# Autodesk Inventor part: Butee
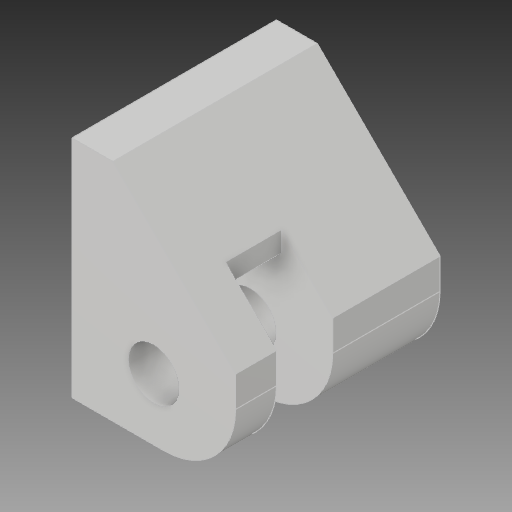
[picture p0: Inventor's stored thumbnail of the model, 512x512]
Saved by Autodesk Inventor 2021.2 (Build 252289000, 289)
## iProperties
Created: 2018-06
Part Number: Butee
Material: Plastique ABS
Document SubType Name: Modeling
Designer: Fabian Perrée
Density: 1.06 g/cm^3
Appearance: Lisse - Blanc
Author: Fabian Perrée
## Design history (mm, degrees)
sketch "Esquisse1"
  geometry: L1 (0, 0)-(0, 13); L2 (0, 22)-(4, 22); L3 (4, 22)-(11, 15); L4 (16, 10)-(16, 7); L5 (9, 0)-(0, 0); L6 (0, 13)-(11, 13); L7 (11, 13)-(11, 15); L8 (11, 15)-(16, 10); L9 (0, 13)-(0, 22); C1 r 2.5 at (8, 6); A1 r 7 centre (9, 7) between (9, 0) and (16, 7); 1 further point
  constraints: 18 end point, 4 perpendicular, 2 centre point, 2 parallel, 2 point on circle, 2 point on line, 2 tangent, 2 vertical, 1 collinear, 1 horizontal
  dimensions: "d1" = 4 distance of L2.start L2.end; "d2" = 135 deg angle of L2 L3; "d3" = 5 diameter of C1; "d4" = 6 distance from line of L5 C1.centre; "d5" = 8 distance from line of L1 C1.centre; "d7" = 7 radius of A1; "d9" = 3 distance from line of C1.centre L7; "d18" = 13 distance between parallel lines of L5 L6; "d20" = 16 distance from line of L2 C1.centre; "d21" = 16 distance between parallel lines of L4 L1
extrude "Extrusion1" new body sketch "Esquisse1" distance "d10" = 4; taper "d12" = 0 deg; dims "d11" = 16, "d13" = 0
extrude "Extrusion2" join sketch "Esquisse1" distance "d14" = 4; taper "d15" = 0 deg
node "Plan de construction1"
node "Plan de construction2"
extrude "Extrusion3" join sketch "Esquisse1" stored distance "d16" = 10; taper "d17" = 0 deg
node "Solide1"
other parameters: "d19" = 5.5
